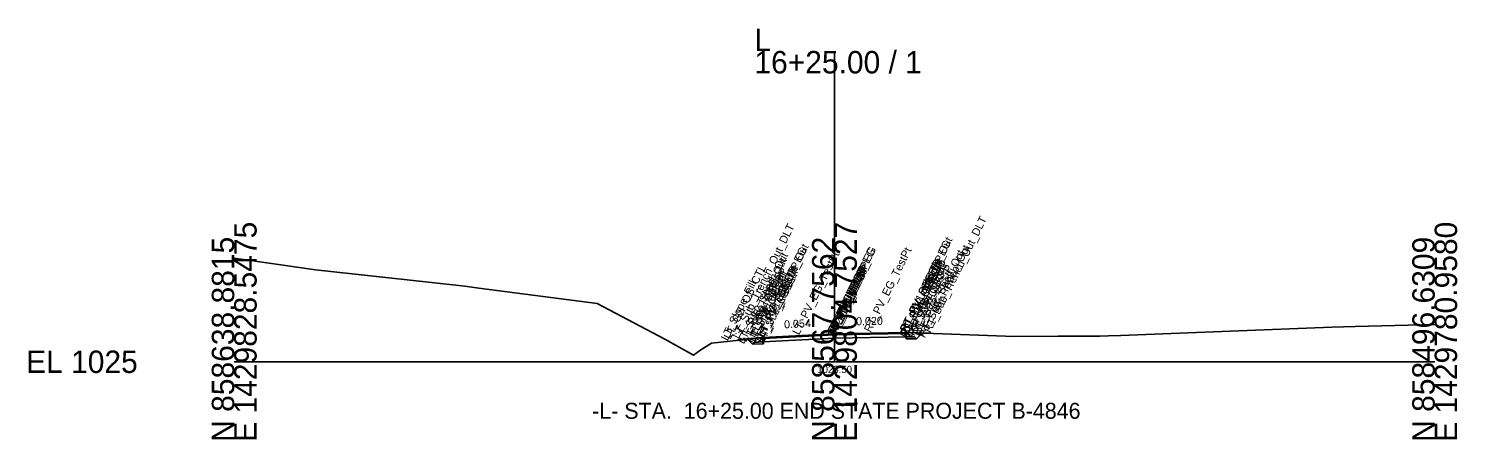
# Model space of a CAD drawing. Extents: x -26 to 153, y -10 to 13058.
# Drawn here: x -25.7 to 152.8, y 9490.3 to 9541.6 of the extents above; entities that cross this region are included whole.
import ezdxf

# ---------------------------------------------------------------- set-up
doc = ezdxf.new("R2010")
doc.units = 0
for name, color, linetype in [('Default', 7, 'Continuous'), ('Exist Cross Section Cell', 7, 'Continuous'), ('Exist XS Center Line Elevation Label', 7, 'Continuous'), ('Exist XS Ground Line', 7, 'Continuous'), ('Prop CMT Pvmt Course 1', 7, 'Continuous'), ('Prop CMT Pvmt Course 2', 7, 'Continuous'), ('Prop CMT Pvmt Surface', 7, 'Continuous'), ('Prop CMT Pvmt Surface Shoulder', 7, 'Continuous'), ('Prop CMT Pvmt Wedge Surface 1', 7, 'Continuous'), ('Prop CMT Pvmt Wedge Surface 2', 7, 'Continuous'), ('Prop CMT Shld Paved Course 1', 7, 'Continuous'), ('Prop CMT Shld Paved Course 2', 7, 'Continuous'), ('Prop CMT Slope Grass', 7, 'Continuous'), ('Prop CMT Subgrade Earthwork', 7, 'Continuous'), ('Prop XS Dump Level', 7, 'Continuous'), ('Prop XS SE Text', 7, 'Continuous'), ('Prop XS Side Slope Text', 7, 'Continuous'), ('Prop XSC Text', 7, 'Continuous')]:
    doc.layers.add(name, color=color, linetype=linetype)

msp = doc.modelspace()

# ---------------------------------------------------------------- linework, layer by layer
at = {"layer": 'Exist Cross Section Cell'}
for p, q in [((75, 9500), (75, 9538.8)), ((0, 9500), (75, 9500)), ((75, 9500), (150, 9500))]:
    msp.add_line(p, q, dxfattribs=at)
at = {"layer": 'Exist XS Ground Line'}
msp.add_lwpolyline([(0, 9512.93), (4.35, 9512.29), (10.14, 9511.47), (24.29, 9509.92), (28.8, 9509.45), (30.55, 9509.21), (45.36, 9507.29), (53.8, 9502.82), (57.37, 9500.84), (58.29, 9501.48), (59.65, 9502.32), (65.47, 9502.95), (66.08, 9503.02), (66.51, 9503.04), (74.92, 9503.49), (79.94, 9503.59), (84.01, 9503.67), (97.48, 9503.15), (102.94, 9503.18), (108.14, 9503.2), (109.24, 9503.22), (110.78, 9503.29), (124.43, 9503.83), (137.15, 9504.31), (140.05, 9504.4), (150, 9504.65)], dxfattribs=at)
at = {"layer": 'Prop CMT Pvmt Course 1'}
for points in [[(75, 9503.5), (66.05, 9503.01)], [(66.14, 9502.89), (75, 9503.37)], [(75, 9503.5), (83.95, 9503.67)], [(83.95, 9503.55), (75, 9503.37)], [(75, 9502.95), (75, 9503.5)], [(75, 9502.95), (75, 9503.5)], [(75, 9503.37), (75, 9502.95), (75, 9502.95)], [(75, 9503.37), (75, 9502.95), (75, 9502.95)], [(83.95, 9503.67), (83.95, 9503.13), (83.95, 9503.13), (83.95, 9503.55)], [(66.05, 9503.01), (66.05, 9502.47)], [(66.05, 9502.47), (66.14, 9502.48)], [(66.14, 9502.48), (66.14, 9502.89)]]:
    msp.add_lwpolyline(points, dxfattribs=at)
at = {"layer": 'Prop CMT Pvmt Course 2'}
for points in [[(66.14, 9502.48), (66.05, 9502.47)], [(66.05, 9502.47), (66.05, 9502.22)], [(66.05, 9502.22), (66.14, 9502.23)], [(66.14, 9502.23), (66.14, 9502.48)], [(83.95, 9502.88), (83.95, 9502.88), (83.95, 9503.13), (83.95, 9503.13)], [(83.95, 9503.13), (83.95, 9502.88)]]:
    msp.add_lwpolyline(points, dxfattribs=at)
at = {"layer": 'Prop CMT Pvmt Surface'}
for points in [[(75, 9503.5), (66.05, 9503.01)], [(75, 9503.5), (83.95, 9503.67)]]:
    msp.add_lwpolyline(points, dxfattribs=at)
at = {"layer": 'Prop CMT Pvmt Surface Shoulder'}
for points in [[(83.95, 9503.67), (83.95, 9503.67)], [(66.05, 9503.01), (66.05, 9503.01)]]:
    msp.add_lwpolyline(points, dxfattribs=at)
at = {"layer": 'Prop CMT Pvmt Wedge Surface 1'}
for points in [[(75, 9503.37), (66.14, 9502.89)], [(75, 9503.37), (83.95, 9503.55)], [(75, 9503.5), (75, 9502.95), (75, 9502.95), (75, 9503.37)], [(75, 9503.5), (75, 9502.95), (75, 9502.95), (75, 9503.37)], [(83.95, 9503.13), (83.95, 9503.67)], [(83.95, 9503.55), (83.95, 9503.13), (83.95, 9503.13)], [(66.05, 9502.47), (66.05, 9503.01)], [(66.14, 9502.48), (66.05, 9502.47)], [(66.14, 9502.89), (66.14, 9502.48)]]:
    msp.add_lwpolyline(points, dxfattribs=at)
at = {"layer": 'Prop CMT Pvmt Wedge Surface 2'}
for points in [[(75, 9503.5), (75, 9502.95)], [(75, 9503.5), (75, 9502.95)], [(83.95, 9503.13), (83.95, 9503.67)], [(66.05, 9502.47), (66.05, 9503.01)], [(75, 9502.95), (66.05, 9502.47)], [(75, 9502.95), (83.95, 9503.13)]]:
    msp.add_lwpolyline(points, dxfattribs=at)
at = {"layer": 'Prop CMT Shld Paved Course 1'}
for points in [[(83.95, 9503.67), (83.95, 9503.67)], [(83.95, 9503.67), (84.5, 9503.12)], [(83.95, 9503.13), (83.95, 9503.67)], [(66.05, 9503.01), (65.5, 9502.46)], [(65.5, 9502.46), (66.05, 9502.47)], [(66.05, 9503.01), (66.05, 9503.01)], [(66.05, 9502.47), (66.05, 9503.01)], [(84.5, 9503.12), (83.95, 9503.13)]]:
    msp.add_lwpolyline(points, dxfattribs=at)
at = {"layer": 'Prop CMT Shld Paved Course 2'}
for points in [[(66.05, 9502.47), (65.5, 9502.46), (65, 9502.45), (64.74, 9502.19)], [(64.74, 9502.19), (66.05, 9502.22)], [(66.05, 9502.22), (66.05, 9502.47)], [(83.95, 9503.13), (84.5, 9503.12), (85, 9503.11), (85.26, 9502.86)], [(83.95, 9502.88), (83.95, 9503.13)], [(85.26, 9502.86), (83.95, 9502.88)]]:
    msp.add_lwpolyline(points, dxfattribs=at)
at = {"layer": 'Prop CMT Slope Grass'}
for points in [[(83.95, 9503.67), (86.95, 9503.56)], [(66.05, 9503.01), (63.05, 9502.77), (62.84, 9502.67)]]:
    msp.add_lwpolyline(points, dxfattribs=at)
at = {"layer": 'Prop CMT Subgrade Earthwork'}
for points in [[(83.95, 9502.88), (83.94, 9503.67)], [(85.26, 9502.86), (86, 9503.6)], [(64.74, 9502.19), (64.08, 9502.85)], [(66.05, 9502.22), (64.74, 9502.19)], [(66.14, 9502.23), (66.05, 9502.22)], [(66.14, 9502.23), (66.16, 9503.02)], [(83.95, 9502.88), (83.95, 9502.88)], [(83.95, 9502.88), (85.26, 9502.86)]]:
    msp.add_lwpolyline(points, dxfattribs=at)

# ---------------------------------------------------------------- texts
at = {"layer": 'Default'}
msp.add_text('-', height=0.0001, dxfattribs=at).set_placement((0, 9500))
at = {"layer": 'Exist Cross Section Cell'}
for s, p in [('L', (65, 9538.8)), ('16+25.00 / 1', (65, 9536)), ('EL 1025', (-26, 9498.6))]:
    msp.add_text(s, height=2.8, dxfattribs=at).set_placement(p)
for s, p in [('E 1429828.5475', (2.8, 9490)), ('E 1429804.7527', (77.8, 9490)), ('E 1429780.9580', (152.8, 9490)), ('N 858638.8815', (0, 9490)), ('N 858567.7562', (75, 9490)), ('N 858496.6309', (150, 9490))]:
    msp.add_text(s, height=2.8, rotation=90, dxfattribs=at).set_placement(p)
at = {"layer": 'Exist XS Center Line Elevation Label'}
msp.add_text('1028.50', height=0.9, dxfattribs=at).set_placement((72.85, 9498.6))
msp.add_text('1028.50', height=0.9, dxfattribs=at).set_placement((72.85, 9498.6))
msp.add_text('1028.50', height=0.9, dxfattribs=at).set_placement((72.85, 9498.6))
at = {"layer": 'Prop XS Dump Level'}
for s, p in [('RT_Sub_Trench_Out_DLT', (86.97, 9503.54)), ('LT_Sub_Trench_Out_DLT', (63.03, 9502.8)), ('LT_PV_OEEOP_EG', (66.14, 9503.02)), ('LT_PV_Sub_Tie_Out', (66.16, 9503.02)), ('RT_PV_IEEOP_EG', (75, 9503.5)), ('LT_PV_IEEOP_EG', (75, 9503.5)), ('RT_PV_EG_TestPt', (79.52, 9503.59)), ('RT_PV_Sub_Tie_Out', (84.02, 9503.67)), ('RT_PV_OEEOP_EG', (84.03, 9503.67)), ('RT_Sub_Trench_Out', (86.31, 9502.88)), ('LT_Sub_Trench_Out', (63.69, 9502.14)), ('LT_PS2_Shelf_Out', (63.95, 9502.39)), ('LT_PV1_OEEOP', (66.14, 9502.89)), ('LT_PV_EG_TestPt', (70.57, 9503.26)), ('RT_PV1_IEEOP', (75, 9503.37)), ('LT_PV1_IEEOP', (75, 9503.37)), ('RT_PV1_OEEOP', (84.03, 9503.55)), ('RT_PV2_OEEOP', (84.03, 9503.14)), ('RT_Sub_OEEOP', (84.03, 9502.89)), ('RT_PV1_OEOT', (85, 9503.7)), ('RT_PS1_OEOP', (85, 9503.7)), ('RT_PS2_Shelf_Out', (86.05, 9503.13)), ('LT_GS_OS_CTL', (62, 9502.72)), ('LT_PS2_OEOP', (64.45, 9502.4)), ('LT_PV1_OEOT', (65, 9502.96)), ('LT_PS1_OEOP', (65, 9502.96)), ('LT_PV2_OEOT', (65, 9502.42)), ('LT_Sub_OEOT', (65, 9502.17)), ('LT_PV2_OEEOP', (66.14, 9502.48)), ('LT_Sub_OEEOP', (66.14, 9502.23)), ('RT_PV2_IEEOP', (75, 9502.96)), ('LT_PV2_IEEOP', (75, 9502.96)), ('RT_PV2_OEOT', (85, 9503.16)), ('RT_Sub_OEOT', (85, 9502.91)), ('RT_PS2_OEOP', (85.55, 9503.14)), ('LT_Slope_Fill', (61.64, 9502.54)), ('PV1_PGL', (75, 9503.5)), ('PV2_PGL', (75, 9502.96))]:
    msp.add_text(s, height=1, rotation=63.5833, dxfattribs=at).set_placement(p)
at = {"layer": 'Prop XS SE Text'}
for s, rotation, p in [('0.054', 3.091, (68.73, 9504.16)), ('0.020', 1.1458, (77.71, 9504.55))]:
    msp.add_text(s, height=1, rotation=rotation, dxfattribs=at).set_placement(p)
at = {"layer": 'Prop XS Side Slope Text'}
msp.add_text('2:1', height=1, rotation=26.5651, dxfattribs=at).set_placement((61.9, 9503.04))
at = {"layer": 'Prop XSC Text'}
msp.add_text('-L- STA.  16+25.00 END STATE PROJECT B-4846', height=2, dxfattribs=at).set_placement((44.73, 9492.88))

doc.saveas('drawing.dxf')
